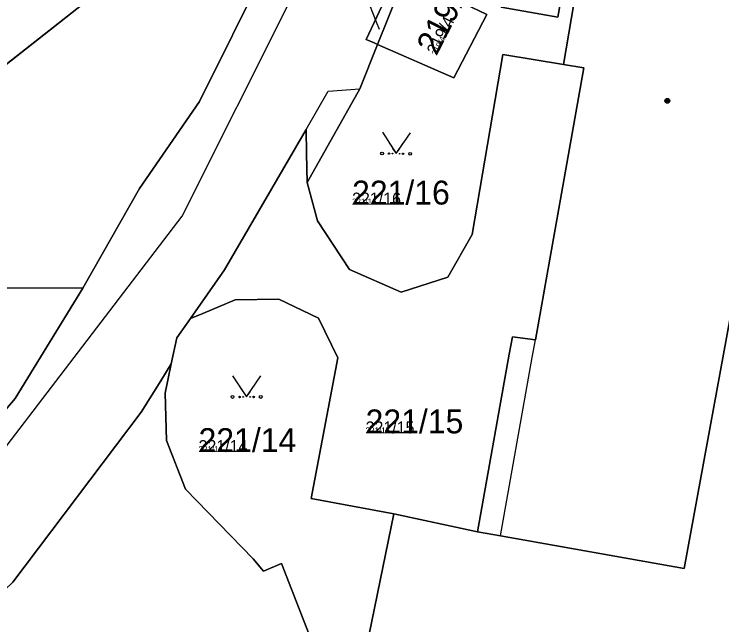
# Model space of a CAD drawing. Extents: x -759873 to -758487, y -975024 to -973516.
# Drawn here: x -759294.8 to -759244.5, y -974695.6 to -974652.2 of the extents above; entities that cross this region are included whole.
import ezdxf

# ---------------------------------------------------------------- set-up
doc = ezdxf.new("R2010")
doc.units = 0
for name, color, linetype in [('KAT_02_hranice parcel', 7, 'Continuous'), ('KAT_03_1000_čísla parcelní', 7, 'Continuous'), ('KAT_03_250_čísla parcelní', 7, 'Continuous'), ('KAT_03_500_čísla parcelní', 7, 'Continuous'), ('KAT_04_vnitřní kresba', 7, 'Continuous'), ('KAT_05_1000_značky kultur', 7, 'Continuous'), ('KAT_05_250_značky kultur', 7, 'Continuous'), ('KAT_05_500_značky kultur', 7, 'Continuous'), ('KAT_07_1000_značky budov', 7, 'Continuous'), ('KAT_07_250_značky budov', 7, 'Continuous'), ('KAT_07_500_značky budov', 7, 'Continuous'), ('KAT_12_pomocná šipka', 7, 'Continuous'), ('KAT_14_plocha_pozemek', 7, 'Continuous')]:
    doc.layers.add(name, color=color, linetype=linetype)

msp = doc.modelspace()

# ---------------------------------------------------------------- linework, layer by layer
at = {"layer": 'KAT_02_hranice parcel'}
for p, q in [((-759290.03, -974651.55), (-759297.43, -974657.37)), ((-759261.87, -974689.03), (-759267.81, -974687.75))]:
    msp.add_line(p, q, dxfattribs=at)
for points in [[(-759289.93, -974671.68), (-759285.91, -974664.61), (-759281.65, -974658.4), (-759272.2, -974639.41), (-759266.15, -974631.32), (-759261.35, -974613.2), (-759262.14, -974589.28), (-759265.86, -974568.96), (-759269.34, -974558.76), (-759272.46, -974550.18)], [(-759268.98, -974654.35), (-759269.23, -974654.24), (-759269.79, -974653.99), (-759263.24, -974640.05)], [(-759264.73, -974643.77), (-759267.55, -974650.8), (-759268.98, -974654.35)], [(-759259.6, -974648.31), (-759260.08, -974651.14), (-759260.18, -974651.71), (-759256.16, -974652.41), (-759255.07, -974646.3), (-759254.91, -974645.39), (-759254.26, -974645.52), (-759254.02, -974645.57), (-759255.75, -974655.78)], [(-759268.98, -974654.35), (-759263.56, -974656.73), (-759261.21, -974652.23), (-759262.8, -974651.45), (-759260.99, -974647.65), (-759259.6, -974648.31)], [(-759273.99, -974664.17), (-759270.24, -974657.51), (-759268.98, -974654.35)], [(-759255.75, -974655.78), (-759260.07, -974655.07), (-759262.26, -974667.86), (-759263.97, -974670.91), (-759267.3, -974671.98), (-759270.97, -974670.35), (-759273.24, -974666.9), (-759273.99, -974664.17)], [(-759255.75, -974655.78), (-759254.3, -974656.02), (-759257.75, -974675.37), (-759259.39, -974675.14), (-759259.61, -974676.38), (-759261.87, -974689.03)], [(-759282.29, -974673.85), (-759279.86, -974670.39), (-759274.06, -974660.4), (-759274.03, -974662.11), (-759273.99, -974664.17)], [(-759261.87, -974689.03), (-759260.23, -974689.3), (-759247.18, -974691.63), (-759243.2, -974670.06)], [(-759289.93, -974671.68), (-759292.94, -974676.6), (-759294.74, -974679.54), (-759302.19, -974688.3), (-759308.07, -974693.53), (-759315.75, -974698.43)], [(-759297.89, -974671.72), (-759295.6, -974671.66), (-759289.93, -974671.68)], [(-759267.81, -974687.75), (-759273.69, -974686.66), (-759271.8, -974676.65), (-759273.17, -974673.82), (-759276.01, -974672.46), (-759279.11, -974672.52), (-759281.41, -974673.48), (-759282.29, -974673.85)], [(-759283.65, -974677.06), (-759283.26, -974675.23), (-759282.29, -974673.85)], [(-759310.73, -974705.56), (-759302.37, -974699.71), (-759294.92, -974692.6), (-759285.8, -974680.51), (-759284.4, -974678.27), (-759283.65, -974677.06)], [(-759274.71, -974708.8), (-759273.27, -974704.19), (-759273.51, -974697.17), (-759275.8, -974691.27), (-759277.1, -974691.83), (-759277.83, -974690.95), (-759282.64, -974685.99), (-759283.98, -974682.52), (-759284.09, -974679.16), (-759283.65, -974677.06)], [(-759267.81, -974687.75), (-759270.96, -974703.01), (-759272, -974708.62)]]:
    msp.add_lwpolyline(points, dxfattribs=at)
at = {"layer": 'KAT_04_vnitřní kresba'}
for p, q in [((-759282.87, -974666.56), (-759269.73, -974640.3)), ((-759274.06, -974660.4), (-759272.48, -974657.67)), ((-759272.48, -974657.67), (-759270.24, -974657.51)), ((-759300.76, -974689.96), (-759282.87, -974666.56)), ((-759257.97, -974676.61), (-759257.75, -974675.37)), ((-759260.23, -974689.3), (-759257.97, -974676.61))]:
    msp.add_line(p, q, dxfattribs=at)
at = {"layer": 'KAT_05_1000_značky kultur'}
for points in [[(-759268.634, -974660.602), (-759267.66, -974662.12), (-759266.634, -974660.636)], [(-759279.29, -974677.929), (-759278.29, -974679.43), (-759277.29, -974677.929)]]:
    msp.add_lwpolyline(points, dxfattribs=at)
for centre in [(-759268.66, -974662.102), (-759266.66, -974662.137), (-759279.29, -974679.429), (-759277.29, -974679.429)]:
    msp.add_circle(centre, 0.1, dxfattribs=at)
at = {"layer": 'KAT_05_250_značky kultur'}
for points in [[(-759267.904, -974661.741), (-759267.66, -974662.12), (-759267.404, -974661.749)], [(-759278.54, -974679.055), (-759278.29, -974679.43), (-759278.04, -974679.055)]]:
    msp.add_lwpolyline(points, dxfattribs=at)
for centre in [(-759267.91, -974662.116), (-759267.41, -974662.124), (-759278.54, -974679.43), (-759278.04, -974679.43)]:
    msp.add_circle(centre, 0.025, dxfattribs=at)
at = {"layer": 'KAT_05_500_značky kultur'}
for points in [[(-759268.147, -974661.361), (-759267.66, -974662.12), (-759267.147, -974661.378)], [(-759278.79, -974678.679), (-759278.29, -974679.43), (-759277.79, -974678.679)]]:
    msp.add_lwpolyline(points, dxfattribs=at)
for centre in [(-759268.16, -974662.111), (-759267.16, -974662.128), (-759278.79, -974679.43), (-759277.79, -974679.43)]:
    msp.add_circle(centre, 0.05, dxfattribs=at)
at = {"layer": 'KAT_07_1000_značky budov'}
msp.add_circle((-759248.367, -974658.359), 0.175, dxfattribs=at)
at = {"layer": 'KAT_07_250_značky budov'}
msp.add_circle((-759248.362, -974658.36), 0.0437, dxfattribs=at)
at = {"layer": 'KAT_07_500_značky budov'}
msp.add_circle((-759248.363, -974658.36), 0.0875, dxfattribs=at)
at = {"layer": 'KAT_12_pomocná šipka'}
for p, q in [((-759269.05, -974652.77), (-759270.125, -974649.968)), ((-759268.85, -974653.29), (-759269.05, -974652.77))]:
    msp.add_line(p, q, dxfattribs=at)
at = {"layer": 'KAT_14_plocha_pozemek'}
for points in [[(-759272.2, -974639.41), (-759281.65, -974658.4), (-759285.91, -974664.61), (-759289.93, -974671.68), (-759292.94, -974676.6), (-759294.74, -974679.54), (-759302.19, -974688.3), (-759308.07, -974693.53), (-759315.75, -974698.43), (-759315.34, -974698.65), (-759317.07, -974700.43), (-759318.71, -974700.17), (-759321.9, -974701.95), (-759356.72, -974718.32), (-759357.54, -974720.88), (-759360.14, -974721.06), (-759370.17, -974725.64), (-759407.29, -974742.88), (-759417.45, -974747.54), (-759420.68, -974749.02), (-759440.41, -974758.08), (-759470.53, -974765.37)], [(-759290.03, -974651.55), (-759297.43, -974657.37), (-759297.89, -974671.72), (-759295.6, -974671.66), (-759289.93, -974671.68), (-759285.91, -974664.61), (-759281.65, -974658.4), (-759272.2, -974639.41)], [(-759273.99, -974664.17), (-759270.24, -974657.51), (-759268.98, -974654.35), (-759269.23, -974654.24), (-759269.79, -974653.99), (-759263.24, -974640.05)], [(-759195.53, -974640.4), (-759198.47, -974656.8), (-759196.04, -974657.25), (-759200.72, -974684.3), (-759206.62, -974683.16), (-759207.63, -974688.9), (-759219.83, -974686.78), (-759220.52, -974690.67), (-759222.01, -974690.43), (-759230.57, -974688.92), (-759230.95, -974691.23), (-759234.88, -974690.51), (-759233.51, -974682.56), (-759234.25, -974677.64), (-759236.71, -974673.33), (-759238.84, -974671.52), (-759241.38, -974670.35), (-759243.2, -974670.06), (-759247.18, -974691.63), (-759260.23, -974689.3), (-759261.87, -974689.03), (-759267.81, -974687.75), (-759270.96, -974703.01)], [(-759254.02, -974645.57), (-759255.75, -974655.78), (-759254.3, -974656.02), (-759257.75, -974675.37), (-759259.39, -974675.14), (-759259.61, -974676.38), (-759261.87, -974689.03), (-759260.23, -974689.3), (-759247.18, -974691.63), (-759243.2, -974670.06), (-759242.5, -974666.11), (-759239.81, -974650.31)], [(-759260.18, -974651.71), (-759256.16, -974652.41), (-759255.07, -974646.3)], [(-759457.27, -974659.49), (-759455.34, -974659.43), (-759441.44, -974658.94), (-759435.79, -974658.58), (-759413.67, -974657.28), (-759400.09, -974656.56), (-759393.93, -974656.47), (-759392.25, -974656.43), (-759382.08, -974656.13), (-759353.25, -974656.6), (-759323.44, -974656.84), (-759309.76, -974657.01), (-759300.66, -974657.21), (-759297.43, -974657.37), (-759290.03, -974651.55)], [(-759459.82, -974776.57), (-759452, -974776.85), (-759432.32, -974766.17), (-759431.64, -974765.8), (-759424.93, -974762.5), (-759393.08, -974746.85), (-759368.71, -974735.24), (-759338.69, -974720.79), (-759334.79, -974718.9), (-759324.54, -974713.59), (-759321.22, -974711.76), (-759310.73, -974705.56), (-759302.37, -974699.71), (-759294.92, -974692.6), (-759285.8, -974680.51), (-759284.4, -974678.27), (-759283.65, -974677.06), (-759283.26, -974675.23), (-759282.29, -974673.85), (-759279.86, -974670.39), (-759274.06, -974660.4), (-759274.03, -974662.11), (-759273.99, -974664.17)]]:
    msp.add_lwpolyline(points, dxfattribs=at)
for points in [[(-759263.24, -974640.05), (-759269.79, -974653.99), (-759269.23, -974654.24), (-759268.98, -974654.35), (-759267.55, -974650.8), (-759264.73, -974643.77)], [(-759261.21, -974652.23), (-759262.8, -974651.45), (-759260.99, -974647.65), (-759259.6, -974648.31), (-759259.08, -974645.28), (-759258.99, -974644.73), (-759264.73, -974643.77), (-759267.55, -974650.8), (-759268.98, -974654.35), (-759263.56, -974656.73)], [(-759268.98, -974654.35), (-759270.24, -974657.51), (-759273.99, -974664.17), (-759273.24, -974666.9), (-759270.97, -974670.35), (-759267.3, -974671.98), (-759263.97, -974670.91), (-759262.26, -974667.86), (-759260.07, -974655.07), (-759255.75, -974655.78), (-759254.02, -974645.57), (-759254.26, -974645.52), (-759254.91, -974645.39), (-759255.07, -974646.3), (-759256.16, -974652.41), (-759260.18, -974651.71), (-759260.08, -974651.14), (-759259.6, -974648.31), (-759260.99, -974647.65), (-759262.8, -974651.45), (-759261.21, -974652.23), (-759263.56, -974656.73)], [(-759262.26, -974667.86), (-759263.97, -974670.91), (-759267.3, -974671.98), (-759270.97, -974670.35), (-759273.24, -974666.9), (-759273.99, -974664.17), (-759274.03, -974662.11), (-759274.06, -974660.4), (-759279.86, -974670.39), (-759282.29, -974673.85), (-759281.41, -974673.48), (-759279.11, -974672.52), (-759276.01, -974672.46), (-759273.17, -974673.82), (-759271.8, -974676.65), (-759273.69, -974686.66), (-759267.81, -974687.75), (-759261.87, -974689.03), (-759259.61, -974676.38), (-759259.39, -974675.14), (-759257.75, -974675.37), (-759254.3, -974656.02), (-759255.75, -974655.78), (-759260.07, -974655.07)], [(-759341.17, -974684.5), (-759315.75, -974698.43), (-759308.07, -974693.53), (-759302.19, -974688.3), (-759294.74, -974679.54), (-759292.94, -974676.6), (-759289.93, -974671.68), (-759295.6, -974671.66), (-759297.89, -974671.72), (-759300.4, -974671.79), (-759300.24, -974675.67), (-759322.44, -974674.47), (-759348.61, -974673.08), (-759354.65, -974673.32)], [(-759267.81, -974687.75), (-759273.69, -974686.66), (-759271.8, -974676.65), (-759273.17, -974673.82), (-759276.01, -974672.46), (-759279.11, -974672.52), (-759281.41, -974673.48), (-759282.29, -974673.85), (-759283.26, -974675.23), (-759283.65, -974677.06), (-759284.09, -974679.16), (-759283.98, -974682.52), (-759282.64, -974685.99), (-759277.83, -974690.95), (-759277.1, -974691.83), (-759275.8, -974691.27), (-759273.51, -974697.17), (-759273.27, -974704.19), (-759274.71, -974708.8), (-759274.13, -974708.76), (-759272, -974708.62), (-759270.96, -974703.01)], [(-759301.33, -974710.58), (-759315.02, -974711.39), (-759302.61, -974716.66), (-759303.18, -974717.78), (-759297.53, -974720.28), (-759290.54, -974720.81), (-759284.55, -974719.08), (-759278.97, -974715.28), (-759275.08, -974710), (-759274.71, -974708.8), (-759273.27, -974704.19), (-759273.51, -974697.17), (-759275.8, -974691.27), (-759277.1, -974691.83), (-759277.83, -974690.95), (-759282.64, -974685.99), (-759283.98, -974682.52), (-759284.09, -974679.16), (-759283.65, -974677.06), (-759284.4, -974678.27), (-759285.8, -974680.51), (-759294.92, -974692.6), (-759302.37, -974699.71), (-759310.73, -974705.56)]]:
    msp.add_lwpolyline(points, close=True, dxfattribs=at)

# ---------------------------------------------------------------- texts
at = {"layer": 'KAT_03_1000_čísla parcelní'}
msp.add_text('219/4', height=1.7, rotation=63, dxfattribs=at).set_placement((-759264.772, -974655.175))
for s, p in [('221/16', (-759270.79, -974665.74)), ('221/15', (-759269.83, -974682.02)), ('221/14', (-759281.71, -974683.35))]:
    msp.add_text(s, height=1.7, dxfattribs=at).set_placement(p)
at = {"layer": 'KAT_03_250_čísla parcelní'}
msp.add_text('219/4', height=0.425, rotation=63, dxfattribs=at).set_placement((-759264.772, -974655.175))
for s, p in [('221/16', (-759270.79, -974665.74)), ('221/15', (-759269.83, -974682.02)), ('221/14', (-759281.71, -974683.35))]:
    msp.add_text(s, height=0.425, dxfattribs=at).set_placement(p)
at = {"layer": 'KAT_03_500_čísla parcelní'}
msp.add_text('219/4', height=0.85, rotation=63, dxfattribs=at).set_placement((-759264.772, -974655.175))
for s, p in [('221/16', (-759270.79, -974665.74)), ('221/15', (-759269.83, -974682.02)), ('221/14', (-759281.71, -974683.35))]:
    msp.add_text(s, height=0.85, dxfattribs=at).set_placement(p)

doc.saveas('drawing.dxf')
